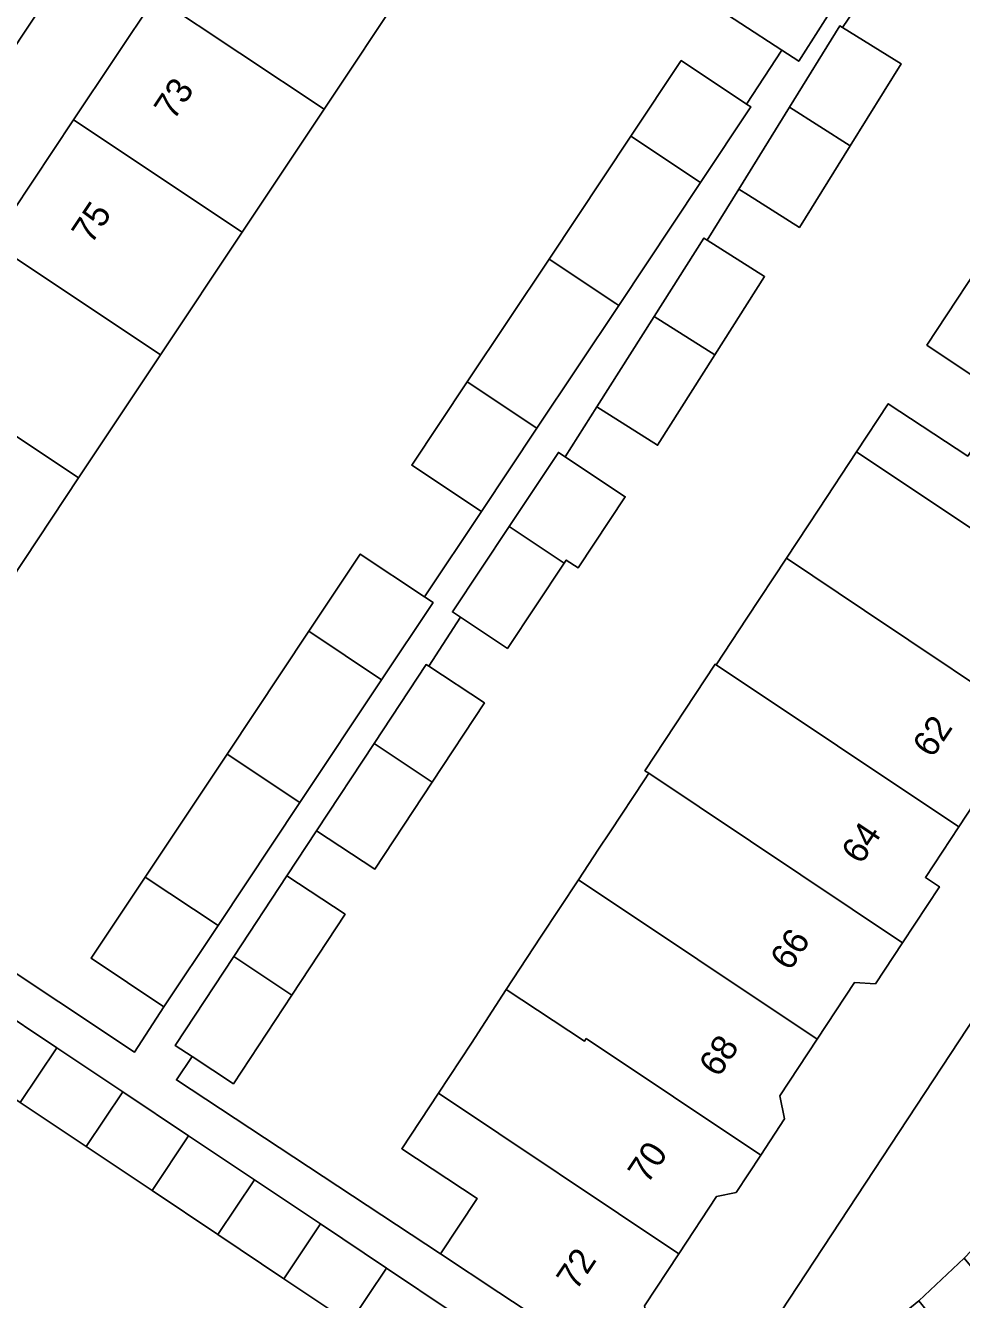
# Model space of a CAD drawing. Extents: x 159279 to 160377, y 384531 to 385888.
# Drawn here: x 159508.58 to 159545.01, y 385140.99 to 385190.61 of the extents above; entities that cross this region are included whole.
import ezdxf

# ---------------------------------------------------------------- set-up
doc = ezdxf.new("R2010")
doc.units = 0
for name, color, linetype in [('IMGEO_Erf', 7, 'Continuous'), ('IMGEO_Pand', 7, 'Continuous'), ('IMGEO_Pand_nummerreeks', 7, 'Continuous'), ('IMGEO_Voetpad_open', 7, 'Continuous')]:
    doc.layers.add(name, color=color, linetype=linetype)

msp = doc.modelspace()

# ---------------------------------------------------------------- linework, layer by layer
at = {"layer": 'IMGEO_Erf'}
for points in [[(159530.535, 385223.584), (159500, 385177.475), (159492.38, 385165.468)], [(159507.261, 385182.153), (159510.446, 385186.939), (159513.632, 385191.726), (159516.817, 385196.513), (159520.098, 385201.443), (159524.261, 385198.673), (159526.667, 385197.072), (159523.384, 385192.138), (159520.198, 385187.351), (159517.013, 385182.564), (159513.827, 385177.778), (159510.641, 385172.99), (159507.456, 385168.204)], [(159535.013, 385135.989), (159573.94, 385195.196)], [(159534.101, 385189.241), (159536.64, 385187.552), (159538.014, 385189.652), (159533.235, 385192.777)], [(159541.558, 385192.285), (159540.385, 385190.527), (159542.664, 385189.118), (159540.681, 385185.929), (159538.701, 385182.745), (159536.717, 385184.003), (159536.346, 385184.238), (159535.115, 385182.247), (159537.35, 385180.829), (159535.416, 385177.778), (159533.185, 385174.26), (159530.821, 385175.759), (159529.584, 385173.807), (159530.332, 385173.31), (159531.925, 385172.253), (159530.086, 385169.483), (159529.625, 385169.789), (159529.542, 385169.664), (159527.34, 385166.346), (159525.505, 385167.564), (159524.273, 385165.653), (159526.442, 385164.224), (159524.409, 385161.14), (159522.178, 385157.754), (159519.91, 385159.249), (159518.75, 385157.489), (159521.019, 385155.995), (159518.94, 385152.841), (159516.669, 385149.394), (159515.067, 385150.45), (159514.453, 385149.541), (159524.73, 385142.766), (159526.155, 385144.928), (159523.224, 385146.86), (159524.65, 385149.024), (159525.94, 385150.981), (159527.284, 385153.06), (159528.628, 385155.099), (159530.102, 385157.335), (159530.889, 385158.53), (159531.338, 385159.211), (159532.669, 385161.231), (159532.836, 385161.485), (159532.688, 385161.584), (159535.423, 385165.734), (159535.462, 385165.708), (159536.659, 385167.525), (159538.197, 385169.859), (159539.456, 385171.77), (159540.932, 385174.01), (159542.165, 385175.88), (159545.258, 385173.842)], [(159500.989, 385158.486), (159512.815, 385150.618), (159513.968, 385152.396), (159511.132, 385154.283), (159513.235, 385157.444), (159516.422, 385162.232), (159519.605, 385167.017), (159521.605, 385170.023), (159524.114, 385168.354), (159526.327, 385171.679), (159523.615, 385173.484), (159525.773, 385176.728), (159528.959, 385181.514), (159532.145, 385186.302), (159534.101, 385189.241)], [(159546.747, 385176.101), (159543.665, 385178.161), (159546.4, 385182.31)], [(159546.382, 385161.634), (159544.907, 385159.396), (159543.61, 385157.428), (159544.157, 385157.068), (159542.716, 385154.882), (159541.663, 385153.283), (159540.847, 385153.332), (159539.393, 385151.126), (159537.944, 385148.927), (159538.128, 385148.032), (159537.196, 385146.617), (159536.236, 385145.161), (159535.48, 385145.006), (159534.007, 385142.77), (159532.669, 385140.74)], [(159518.635, 385141.802), (159516.069, 385143.517), (159513.503, 385145.232), (159510.937, 385146.948), (159508.371, 385148.663), (159505.805, 385150.378), (159503.239, 385152.093), (159504.664, 385154.224), (159497.479, 385158.937), (159495.985, 385156.692), (159490.429, 385160.388), (159484.85, 385151.066)], [(159513.409, 385118.571), (159528.55, 385131.062), (159526.53, 385132.394), (159529.833, 385137.405), (159529.273, 385137.774), (159526.809, 385134.088), (159522.728, 385136.816), (159523.767, 385138.371), (159521.201, 385140.086), (159518.635, 385141.802)]]:
    msp.add_lwpolyline(points, dxfattribs=at)
at = {"layer": 'IMGEO_Pand'}
for points in [[(159543.737, 385197.173), (159543.294, 385197.463), (159542.314, 385198.104), (159540.523, 385199.275), (159539.552, 385199.91), (159538.761, 385200.427), (159536.009, 385196.219), (159534.841, 385196.983), (159532.434, 385193.301), (159533.235, 385192.777), (159538.014, 385189.652), (159538.676, 385189.219)], [(159523.384, 385192.138), (159516.817, 385196.513), (159513.632, 385191.726), (159520.198, 385187.351)], [(159520.198, 385187.351), (159513.632, 385191.726), (159510.446, 385186.939), (159517.013, 385182.564)], [(159542.664, 385189.118), (159540.385, 385190.527), (159540.276, 385190.594), (159538.318, 385187.427), (159540.681, 385185.929)], [(159536.64, 385187.552), (159534.101, 385189.241), (159532.145, 385186.302), (159534.857, 385184.495), (159536.814, 385187.436)], [(159540.681, 385185.929), (159538.318, 385187.427), (159536.346, 385184.238), (159536.717, 385184.003), (159538.701, 385182.745)], [(159517.013, 385182.564), (159510.446, 385186.939), (159507.261, 385182.153), (159513.827, 385177.778)], [(159534.857, 385184.495), (159532.145, 385186.302), (159528.959, 385181.514), (159531.559, 385179.781), (159531.67, 385179.707)], [(159535.115, 385182.247), (159534.986, 385182.328), (159533.051, 385179.277), (159535.416, 385177.778), (159537.35, 385180.829)], [(159546.4, 385182.31), (159543.665, 385178.161), (159546.747, 385176.101), (159553.559, 385171.548), (159555.067, 385173.836), (159554.604, 385174.141), (159555.833, 385176.006)], [(159513.827, 385177.778), (159507.261, 385182.153), (159504.075, 385177.365), (159510.641, 385172.99)], [(159531.67, 385179.707), (159531.559, 385179.781), (159528.959, 385181.514), (159525.773, 385176.728), (159528.485, 385174.921)], [(159535.416, 385177.778), (159533.051, 385179.277), (159530.821, 385175.759), (159533.185, 385174.26)], [(159510.641, 385172.99), (159504.075, 385177.365), (159500.889, 385172.578), (159507.456, 385168.204)], [(159528.485, 385174.921), (159525.773, 385176.728), (159523.615, 385173.484), (159526.327, 385171.679)], [(159546.747, 385176.101), (159546.615, 385175.901), (159545.258, 385173.842), (159542.165, 385175.88), (159540.932, 385174.01), (159550.378, 385167.697), (159551.949, 385170.082), (159552.694, 385170.235), (159553.559, 385171.548)], [(159531.925, 385172.253), (159530.332, 385173.31), (159529.584, 385173.807), (159529.322, 385173.981), (159527.405, 385171.092), (159529.542, 385169.664), (159529.625, 385169.789), (159530.086, 385169.483)], [(159540.932, 385174.01), (159539.456, 385171.77), (159538.197, 385169.859), (159541.235, 385167.828), (159548.106, 385163.236), (159549.07, 385164.7), (159548.911, 385165.471), (159550.378, 385167.697)], [(159529.542, 385169.664), (159527.405, 385171.092), (159525.198, 385167.768), (159525.505, 385167.564), (159527.34, 385166.346)], [(159524.114, 385168.354), (159521.605, 385170.023), (159519.605, 385167.017), (159522.44, 385165.128), (159524.442, 385168.136)], [(159538.197, 385169.859), (159536.659, 385167.525), (159535.462, 385165.708), (159544.907, 385159.396), (159546.382, 385161.634), (159547.154, 385161.792), (159548.106, 385163.236), (159541.235, 385167.828)], [(159522.44, 385165.128), (159519.605, 385167.017), (159516.422, 385162.232), (159519.257, 385160.344)], [(159524.273, 385165.653), (159524.173, 385165.719), (159522.15, 385162.649), (159524.409, 385161.14), (159526.442, 385164.224)], [(159535.462, 385165.708), (159535.423, 385165.734), (159532.688, 385161.584), (159532.836, 385161.485), (159542.716, 385154.882), (159544.157, 385157.068), (159543.61, 385157.428), (159544.907, 385159.396)], [(159524.409, 385161.14), (159522.15, 385162.649), (159519.91, 385159.249), (159522.178, 385157.754)], [(159519.257, 385160.344), (159516.422, 385162.232), (159513.235, 385157.444), (159516.071, 385155.555)], [(159532.836, 385161.485), (159532.669, 385161.231), (159531.338, 385159.211), (159530.889, 385158.53), (159530.102, 385157.335), (159539.393, 385151.126), (159540.847, 385153.332), (159541.663, 385153.283), (159542.716, 385154.882)], [(159516.071, 385155.555), (159513.235, 385157.444), (159511.132, 385154.283), (159513.968, 385152.396)], [(159518.75, 385157.489), (159516.682, 385154.35), (159518.94, 385152.841), (159521.019, 385155.995)], [(159530.403, 385151.157), (159537.196, 385146.617), (159538.128, 385148.032), (159537.944, 385148.927), (159539.393, 385151.126), (159530.102, 385157.335), (159528.628, 385155.099), (159527.284, 385153.06), (159530.333, 385151.051)], [(159518.94, 385152.841), (159516.682, 385154.35), (159514.401, 385150.889), (159515.067, 385150.45), (159516.669, 385149.394)], [(159530.403, 385151.157), (159530.333, 385151.051), (159527.284, 385153.06), (159525.94, 385150.981), (159524.65, 385149.024), (159534.007, 385142.77), (159535.48, 385145.006), (159536.236, 385145.161), (159537.196, 385146.617)], [(159508.371, 385148.663), (159509.796, 385150.794), (159507.23, 385152.509), (159505.805, 385150.378)], [(159509.796, 385150.794), (159508.371, 385148.663), (159510.937, 385146.948), (159512.362, 385149.079)], [(159513.503, 385145.232), (159514.928, 385147.363), (159512.362, 385149.079), (159510.937, 385146.948)], [(159524.65, 385149.024), (159523.224, 385146.86), (159526.155, 385144.928), (159524.73, 385142.766), (159527.004, 385141.267), (159531.179, 385138.516), (159531.493, 385138.991), (159532.224, 385139.141), (159532.814, 385140.036), (159532.669, 385140.74), (159534.007, 385142.77)], [(159514.928, 385147.363), (159513.503, 385145.232), (159516.069, 385143.517), (159517.494, 385145.648)], [(159518.635, 385141.802), (159520.06, 385143.933), (159517.494, 385145.648), (159516.069, 385143.517)], [(159520.06, 385143.933), (159518.635, 385141.802), (159521.201, 385140.086), (159522.626, 385142.217)], [(159523.767, 385138.371), (159525.192, 385140.502), (159522.626, 385142.217), (159521.201, 385140.086)]]:
    msp.add_lwpolyline(points, close=True, dxfattribs=at)
at = {"layer": 'IMGEO_Voetpad_open'}
for points in [[(159492.38, 385165.468), (159500, 385177.475), (159530.535, 385223.584)], [(159543.737, 385197.173), (159538.676, 385189.219), (159538.014, 385189.652), (159536.64, 385187.552), (159536.814, 385187.436), (159534.857, 385184.495), (159531.67, 385179.707), (159528.485, 385174.921), (159526.327, 385171.679), (159524.114, 385168.354), (159524.442, 385168.136), (159522.44, 385165.128), (159519.257, 385160.344), (159516.071, 385155.555), (159513.968, 385152.396), (159512.815, 385150.618), (159500.989, 385158.486)], [(159573.94, 385195.196), (159535.013, 385135.989), (159534.234, 385134.804), (159531.987, 385136.276), (159528.55, 385131.062), (159513.409, 385118.571)], [(159535.115, 385182.247), (159536.346, 385184.238), (159538.318, 385187.427), (159540.276, 385190.594), (159540.385, 385190.527), (159541.558, 385192.285)], [(159531.179, 385138.516), (159527.004, 385141.267), (159524.73, 385142.766), (159514.453, 385149.541), (159515.067, 385150.45), (159514.401, 385150.889), (159516.682, 385154.35), (159518.75, 385157.489), (159519.91, 385159.249), (159522.15, 385162.649), (159524.173, 385165.719), (159524.273, 385165.653), (159525.505, 385167.564), (159525.198, 385167.768), (159527.405, 385171.092), (159529.322, 385173.981), (159529.584, 385173.807), (159530.821, 385175.759), (159533.051, 385179.277), (159534.986, 385182.328), (159535.115, 385182.247)], [(159507.23, 385152.509), (159509.796, 385150.794), (159512.362, 385149.079), (159514.928, 385147.363), (159517.494, 385145.648), (159520.06, 385143.933), (159522.626, 385142.217), (159525.192, 385140.502)], [(159509.932, 385118.983), (159504.55, 385114.528), (159507.347, 385111.146), (159507.439, 385111.212), (159507.575, 385111.323), (159508.785, 385112.295), (159511.351, 385114.434), (159513.826, 385116.492), (159526.239, 385126.771), (159525.927, 385127.153), (159528.846, 385129.572), (159529.162, 385129.185), (159542.862, 385140.537), (159543.347, 385140.939), (159545.121, 385142.605), (159551.035, 385148.782), (159552.467, 385150.704), (159552.537, 385150.916), (159552.587, 385151.134), (159552.618, 385151.356), (159552.629, 385151.579)]]:
    msp.add_lwpolyline(points, dxfattribs=at)
msp.add_lwpolyline([(159553.225, 385138.493), (159552.781, 385138.729), (159552.318, 385138.925), (159551.84, 385139.078), (159551.349, 385139.188), (159550.851, 385139.254), (159550.349, 385139.275), (159549.847, 385139.252), (159549.349, 385139.183), (159548.859, 385139.07), (159548.381, 385138.914), (159548.224, 385138.852), (159546.712, 385140.681), (159545.121, 385142.605), (159543.347, 385140.939), (159544.838, 385139.116), (159546.248, 385137.391), (159549.148, 385136.186)], close=True, dxfattribs=at)

# ---------------------------------------------------------------- texts
at = {"layer": 'IMGEO_Pand_nummerreeks'}
for s, rotation, p in [('73', 56.3561, (159514.347, 385186.88)), ('75', 56.3561, (159511.138, 385182.056)), ('62', 56.2415, (159543.876, 385162.044)), ('64', 56.2415, (159541.104, 385157.897)), ('66', 56.2415, (159538.331, 385153.749)), ('68', 56.2415, (159535.56, 385149.603)), ('70', 56.2415, (159532.787, 385145.454)), ('72', 56.2415, (159530.011, 385141.301))]:
    msp.add_text(s, height=1, rotation=rotation, dxfattribs=at).set_placement(p)

doc.saveas('drawing.dxf')
